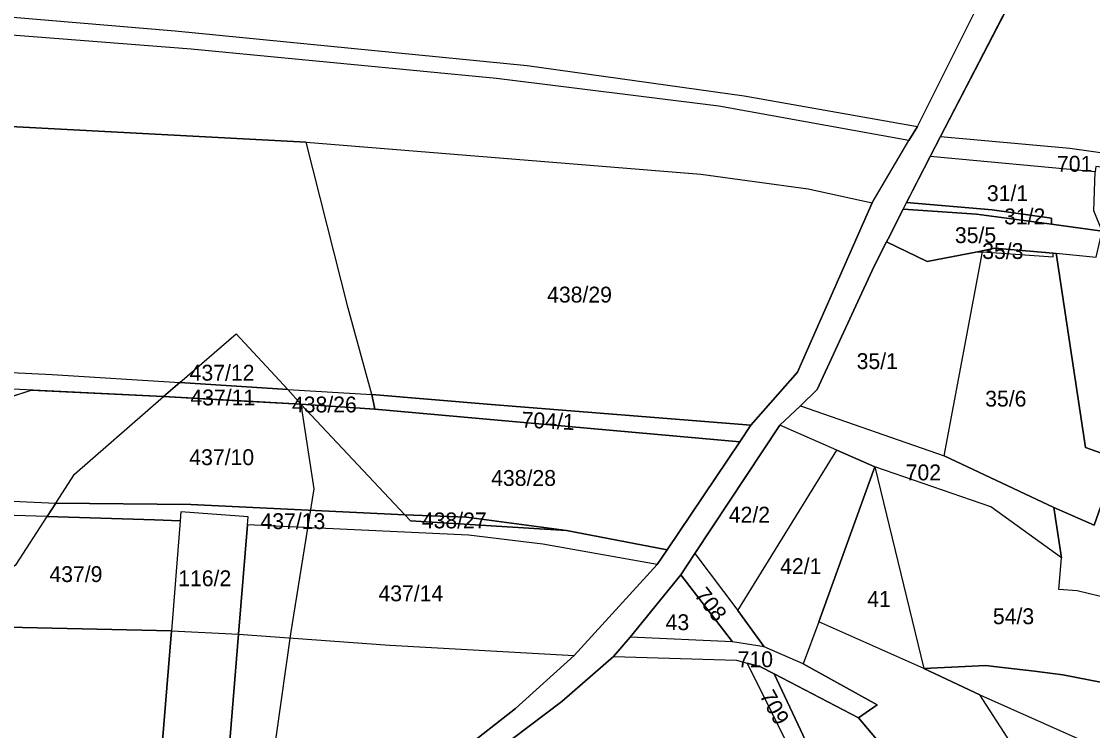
# Model space of a CAD drawing. Extents: x -629983 to -626385, y -1072828 to -1067897.
# Drawn here: x -627674 to -627471.3, y -1070394.2 to -1070260.1 of the extents above; entities that cross this region are included whole.
import ezdxf

# ---------------------------------------------------------------- set-up
doc = ezdxf.new("R2010")
doc.units = 0
for name, color, linetype in [('Parcela nároku', 7, 'Continuous'), ('Parcelní číslo', 7, 'Continuous'), ('Plocha PÚ', 7, 'Continuous'), ('Vnitřní obvod_šetřený', 7, 'Continuous')]:
    doc.layers.add(name, color=color, linetype=linetype)

msp = doc.modelspace()

# ---------------------------------------------------------------- linework, layer by layer
at = {"layer": 'Parcela nároku'}
for points in [[(-628010.32, -1070222.78), (-627867.35, -1070243.48), (-627800.2, -1070247.16), (-627750.66, -1070252.06), (-627712.43, -1070256.17), (-627644.93, -1070261.86), (-627578.29, -1070268.4), (-627537.22, -1070274.1), (-627504.39, -1070279.94), (-627482.04, -1070235.24), (-627493.99, -1070234.25), (-627560.1, -1070227.33), (-627685.83, -1070213.41), (-627710.8, -1070210.1), (-627839.49, -1070195.32), (-627852.52, -1070193.73), (-627931.37, -1070179.87)], [(-628010.32, -1070222.78), (-627867.35, -1070243.48), (-627800.2, -1070247.16), (-627750.66, -1070252.06), (-627712.43, -1070256.17), (-627644.93, -1070261.86), (-627578.29, -1070268.4), (-627537.22, -1070274.1), (-627504.39, -1070279.94), (-627506.01, -1070282.58), (-627542.01, -1070276.06), (-627584.08, -1070270.83), (-627641.87, -1070265.31), (-627692.85, -1070261.34), (-627706.57, -1070260.22), (-627765.59, -1070253.53), (-627842.38, -1070247.97), (-627872.06, -1070246.99), (-627936.13, -1070236.87)], [(-627675.73, -1070497.41), (-627670.84, -1070489.21), (-627664.39, -1070479.79), (-627651.75, -1070462.96), (-627646.33, -1070454.56), (-627642.78, -1070448.49), (-627642.71, -1070448.68), (-627639.15, -1070447.3), (-627640.32, -1070444.28), (-627635.77, -1070436.5), (-627632.18, -1070430.36), (-627626.49, -1070424.12), (-627596.54, -1070402.58), (-627580.46, -1070390.03), (-627569.41, -1070380), (-627553.68, -1070362.8), (-627551.79, -1070360), (-627538.05, -1070339.59), (-627535.93, -1070336.45), (-627527.1, -1070326.43), (-627512.99, -1070294.4), (-627506.01, -1070282.58), (-627504.39, -1070279.94), (-627482.04, -1070235.24)], [(-627943.87, -1070258.43), (-627852.12, -1070267.55), (-627762.73, -1070274.69), (-627694, -1070279.01), (-627620.1, -1070282.88), (-627545.39, -1070288.95), (-627525.09, -1070291.72), (-627512.99, -1070294.4), (-627506.01, -1070282.58), (-627542.01, -1070276.06), (-627584.08, -1070270.83), (-627641.87, -1070265.31), (-627692.85, -1070261.34), (-627706.57, -1070260.22), (-627765.59, -1070253.53), (-627842.38, -1070247.97), (-627872.06, -1070246.99), (-627936.13, -1070236.87)], [(-627484.54, -1070251.9), (-627500.04, -1070281.83), (-627501.98, -1070285.58), (-627506.48, -1070294.32), (-627507.13, -1070295.59), (-627509.97, -1070301.16), (-627510.28, -1070301.76), (-627512.6, -1070306.32), (-627523.41, -1070329.67), (-627526.53, -1070332.79), (-627530.45, -1070336.44), (-627546.52, -1070360.7), (-627549.2, -1070364.77), (-627558.79, -1070376.55), (-627561.95, -1070380.18), (-627571.72, -1070388.7), (-627596.73, -1070407.55)], [(-627693.61, -1070374.29), (-627645.62, -1070375.32), (-627649.31, -1070420.79), (-627636.65, -1070421.82), (-627632.91, -1070375.97), (-627604.25, -1070378.04), (-627569.41, -1070380), (-627580.46, -1070390.03), (-627596.54, -1070402.58), (-627626.49, -1070424.12), (-627639.33, -1070428.04), (-627666.89, -1070426.71), (-627676.98, -1070425.76)]]:
    msp.add_lwpolyline(points, dxfattribs=at)
for points in [[(-627477.24, -1070236.31), (-627484.54, -1070251.9), (-627500.04, -1070281.83), (-627475.57, -1070284), (-627464.35, -1070285.62), (-627429.37, -1070289.04), (-627418.41, -1070263.38), (-627409.42, -1070267.15), (-627420.23, -1070245.71), (-627451.48, -1070240.87)], [(-627694, -1070279.01), (-627762.73, -1070274.69), (-627852.12, -1070267.55), (-627857.41, -1070320.6), (-627807.86, -1070322.13), (-627780.69, -1070322.36), (-627715.75, -1070324.53), (-627668.16, -1070326.84), (-627643.99, -1070328.38), (-627633.37, -1070319.16), (-627623.56, -1070329.68), (-627607.68, -1070330.66), (-627612.15, -1070314.31), (-627620.1, -1070282.88)], [(-627975.41, -1070316.56), (-628013.39, -1070311.63), (-628064.17, -1070304.46), (-628158.28, -1070288.4), (-628169.7, -1070285.94), (-628193.03, -1070281.15), (-628197.85, -1070304.82), (-628163.72, -1070310.89), (-628107.67, -1070319.94), (-627998.49, -1070336.29), (-627905.29, -1070342.7), (-627827.64, -1070345.16), (-627715.35, -1070349), (-627667.5, -1070351.19), (-627663.96, -1070345.7), (-627647.13, -1070331.03), (-627719.77, -1070327.49), (-627789.19, -1070324.83), (-627857.63, -1070323.4), (-627930.45, -1070320.12)], [(-627464.35, -1070285.62), (-627429.37, -1070289.04), (-627431.24, -1070294.08), (-627443.18, -1070290.54), (-627458.17, -1070289.11), (-627470.63, -1070287.47), (-627470.75, -1070288.53), (-627501.98, -1070285.58), (-627500.04, -1070281.83), (-627475.57, -1070284)], [(-627545.39, -1070288.95), (-627525.09, -1070291.72), (-627512.99, -1070294.4), (-627527.1, -1070326.43), (-627535.93, -1070336.45), (-627585.09, -1070332.54), (-627607.68, -1070330.66), (-627612.15, -1070314.31), (-627620.1, -1070282.88)], [(-627479.02, -1070297.25), (-627479.04, -1070298.42), (-627469.42, -1070299.74), (-627471.01, -1070295.88), (-627470.75, -1070288.53), (-627501.98, -1070285.58), (-627506.48, -1070294.32), (-627490.24, -1070295.72)], [(-627469.42, -1070299.74), (-627479.04, -1070298.42), (-627493.23, -1070296.53), (-627507.13, -1070295.59), (-627509.97, -1070301.16), (-627510.28, -1070301.76), (-627502.57, -1070305.47), (-627493.05, -1070303.61), (-627489.75, -1070302.95), (-627478.71, -1070303.86), (-627478.14, -1070303.92), (-627470.55, -1070304.67)], [(-627506.48, -1070294.32), (-627507.13, -1070295.59), (-627493.23, -1070296.53), (-627479.04, -1070298.42), (-627479.02, -1070297.25), (-627490.24, -1070295.72)], [(-627461.62, -1070299.82), (-627455.76, -1070301), (-627448.6, -1070304.07), (-627442.44, -1070308.35), (-627438.26, -1070311.63), (-627421.91, -1070324.46), (-627422.06, -1070324.78), (-627425.91, -1070330.87), (-627428.78, -1070328.99), (-627431.33, -1070333.05), (-627437.16, -1070329.94), (-627441.2, -1070337.83), (-627442.96, -1070336.99), (-627445.44, -1070341.59), (-627447.23, -1070340.65), (-627450.6, -1070346.67), (-627449.35, -1070349.16), (-627453.84, -1070347.28), (-627472.61, -1070340.67), (-627478.14, -1070303.92), (-627470.55, -1070304.67), (-627469.42, -1070299.74)], [(-627512.6, -1070306.32), (-627523.41, -1070329.67), (-627526.53, -1070332.79), (-627499.33, -1070342.21), (-627492.09, -1070303.67), (-627493.05, -1070303.61), (-627502.57, -1070305.47), (-627510.28, -1070301.76)], [(-627478.14, -1070303.92), (-627472.61, -1070340.67), (-627453.84, -1070347.28), (-627449.35, -1070349.16), (-627426.96, -1070358.52), (-627429.07, -1070363.41), (-627455.93, -1070352.67), (-627456.37, -1070353.79), (-627462.61, -1070351.34), (-627468.81, -1070349.21), (-627470.94, -1070355.34), (-627478.59, -1070352.03), (-627499.33, -1070342.21), (-627492.09, -1070303.67), (-627478.71, -1070304.58), (-627478.71, -1070303.86)], [(-627478.71, -1070303.86), (-627489.75, -1070302.95), (-627493.05, -1070303.61), (-627492.09, -1070303.67), (-627478.71, -1070304.58)], [(-627998.49, -1070336.29), (-627905.29, -1070342.7), (-627827.64, -1070345.16), (-627715.35, -1070349), (-627667.5, -1070351.19), (-627669.14, -1070353.74), (-627747.72, -1070351.32), (-627834.23, -1070347.87), (-627862.19, -1070347.87), (-627903.57, -1070346.68), (-627931.89, -1070344.45), (-627993.13, -1070340.27), (-628115.46, -1070322.29), (-628198.34, -1070307.23), (-628197.85, -1070304.82), (-628163.72, -1070310.89), (-628107.67, -1070319.94)], [(-627903.57, -1070346.68), (-627931.89, -1070344.45), (-627993.13, -1070340.27), (-628115.46, -1070322.29), (-628198.34, -1070307.23), (-628203.34, -1070331.74), (-628177.12, -1070337.23), (-628130.58, -1070346.23), (-628080.75, -1070353.83), (-628037.7, -1070359.47), (-627955.53, -1070366.72), (-627892.97, -1070370.2), (-627840.14, -1070371.16), (-627807.49, -1070371.09), (-627701.48, -1070374.12), (-627693.61, -1070374.29), (-627674.98, -1070362.82), (-627669.14, -1070353.74), (-627747.72, -1070351.32), (-627834.23, -1070347.87), (-627862.19, -1070347.87)], [(-627633.37, -1070319.16), (-627623.56, -1070329.68), (-627643.99, -1070328.38)], [(-627668.16, -1070326.84), (-627643.99, -1070328.38), (-627647.13, -1070331.03), (-627719.77, -1070327.49), (-627789.19, -1070324.83), (-627857.63, -1070323.4), (-627857.41, -1070320.6), (-627807.86, -1070322.13), (-627780.69, -1070322.36), (-627715.75, -1070324.53)], [(-627623.56, -1070329.68), (-627621.11, -1070332.45), (-627647.13, -1070331.03), (-627643.99, -1070328.38)], [(-627623.56, -1070329.68), (-627607.68, -1070330.66), (-627607.12, -1070333.41), (-627621.11, -1070332.45)], [(-627663.96, -1070345.7), (-627647.13, -1070331.03), (-627621.11, -1070332.45), (-627601.45, -1070353.4), (-627641.91, -1070351.46), (-627667.5, -1070351.19)], [(-627607.12, -1070333.41), (-627538.05, -1070339.59), (-627551.79, -1070360), (-627570.84, -1070356.36), (-627589.76, -1070353.83), (-627601.45, -1070353.4), (-627621.11, -1070332.45)], [(-627607.68, -1070330.66), (-627585.09, -1070332.54), (-627535.93, -1070336.45), (-627538.05, -1070339.59), (-627607.12, -1070333.41)], [(-627526.53, -1070332.79), (-627499.33, -1070342.21), (-627478.59, -1070352.03), (-627477.14, -1070361.52), (-627490.53, -1070351.87), (-627512.45, -1070344.31), (-627519.69, -1070341.14), (-627530.45, -1070336.44)], [(-627530.45, -1070336.44), (-627546.52, -1070360.7), (-627538.42, -1070371.52), (-627519.69, -1070341.14)], [(-627519.69, -1070341.14), (-627512.45, -1070344.31), (-627523.07, -1070373.63), (-627526.06, -1070381.6), (-627533.41, -1070378.39), (-627538.42, -1070371.52)], [(-627523.07, -1070373.63), (-627512.45, -1070344.31), (-627503.17, -1070382.49)], [(-627428.34, -1070382.69), (-627459.6, -1070371.3), (-627474.17, -1070367.79), (-627477.66, -1070367.54), (-627477.14, -1070361.52), (-627490.53, -1070351.87), (-627512.45, -1070344.31), (-627503.17, -1070382.49), (-627491.48, -1070381.91), (-627489.96, -1070382.08), (-627482.22, -1070382.97), (-627478.87, -1070383.4), (-627476.87, -1070383.66), (-627447.43, -1070389.39), (-627446.08, -1070383.13), (-627429.59, -1070386.99), (-627427.82, -1070383.61)], [(-627477.66, -1070367.54), (-627477.14, -1070361.52), (-627478.59, -1070352.03), (-627470.94, -1070355.34), (-627468.81, -1070349.21), (-627462.61, -1070351.34), (-627456.37, -1070353.79), (-627455.93, -1070352.67), (-627429.07, -1070363.41), (-627426.11, -1070364.59), (-627430.93, -1070374.9), (-627424.08, -1070376.75), (-627419.9, -1070377.83), (-627432.7, -1070392.58), (-627429.59, -1070386.99), (-627427.82, -1070383.61), (-627428.34, -1070382.69), (-627459.6, -1070371.3), (-627474.17, -1070367.79)], [(-627600.39, -1070354.54), (-627570.84, -1070356.36), (-627551.79, -1070360), (-627553.68, -1070362.8), (-627575.31, -1070358.96), (-627589.4, -1070357.26), (-627631.22, -1070355.29), (-627631.1, -1070353.76), (-627643.8, -1070352.84), (-627643.94, -1070354.51), (-627648.82, -1070354.37), (-627669.14, -1070353.74), (-627667.5, -1070351.19), (-627641.91, -1070351.46), (-627601.45, -1070353.4)], [(-627643.94, -1070354.51), (-627645.62, -1070375.32), (-627632.91, -1070375.97), (-627631.22, -1070355.29), (-627631.1, -1070353.76), (-627643.8, -1070352.84)], [(-627693.61, -1070374.29), (-627674.98, -1070362.82), (-627669.14, -1070353.74), (-627648.82, -1070354.37), (-627643.94, -1070354.51), (-627645.62, -1070375.32)], [(-627601.45, -1070353.4), (-627589.76, -1070353.83), (-627570.84, -1070356.36), (-627600.39, -1070354.54)], [(-627631.22, -1070355.29), (-627632.91, -1070375.97), (-627604.25, -1070378.04), (-627569.41, -1070380), (-627553.68, -1070362.8), (-627575.31, -1070358.96), (-627589.4, -1070357.26)], [(-627549.2, -1070364.77), (-627546.52, -1070360.7), (-627538.42, -1070371.52), (-627533.41, -1070378.39), (-627539.38, -1070377.41)], [(-627549.2, -1070364.77), (-627539.38, -1070377.41), (-627558.79, -1070376.55)], [(-627523.07, -1070373.63), (-627526.06, -1070381.6), (-627512.05, -1070389.37), (-627515.53, -1070391.8), (-627509.05, -1070399.5), (-627481.79, -1070434.49), (-627478.35, -1070438.88), (-627472.89, -1070436.01), (-627477.9, -1070426.3), (-627471.88, -1070422.95), (-627485.49, -1070398.49), (-627492.61, -1070387.47), (-627503.17, -1070382.49)], [(-627645.62, -1070375.32), (-627632.91, -1070375.97), (-627636.65, -1070421.82), (-627649.31, -1070420.79)], [(-627539.38, -1070377.41), (-627558.79, -1070376.55), (-627561.95, -1070380.18), (-627538.65, -1070380.92), (-627536.65, -1070381.47), (-627534.08, -1070382.18), (-627531.55, -1070383.49), (-627515.53, -1070391.8), (-627512.05, -1070389.37), (-627526.06, -1070381.6), (-627533.41, -1070378.39)], [(-627550.24, -1070428.21), (-627547.59, -1070432.38), (-627567.3, -1070428.39), (-627579.32, -1070427.13), (-627578.85, -1070417.27), (-627604.65, -1070413.41), (-627596.73, -1070407.55), (-627571.72, -1070388.7), (-627561.95, -1070380.18), (-627538.65, -1070380.92), (-627536.65, -1070381.47), (-627527.29, -1070400.28), (-627520.07, -1070415.67), (-627527.83, -1070420.03), (-627532.81, -1070411.95), (-627539.12, -1070401.72), (-627556.41, -1070413.63), (-627549.89, -1070423.61), (-627547.92, -1070426.74)], [(-627531.55, -1070383.49), (-627534.08, -1070382.18), (-627536.65, -1070381.47), (-627527.29, -1070400.28), (-627524.58, -1070398.23)], [(-627482.22, -1070382.97), (-627489.96, -1070382.08), (-627491.48, -1070381.91), (-627503.17, -1070382.49), (-627492.61, -1070387.47), (-627443.88, -1070409.16), (-627432.7, -1070392.58), (-627447.43, -1070389.39), (-627476.87, -1070383.66), (-627478.87, -1070383.4)], [(-627515.53, -1070391.8), (-627531.55, -1070383.49), (-627524.58, -1070398.23), (-627527.29, -1070400.28), (-627520.07, -1070415.67), (-627509.42, -1070434.62), (-627506.5, -1070439.81), (-627503.29, -1070437.99), (-627497.86, -1070446.25), (-627495.48, -1070449.89), (-627478.35, -1070438.88), (-627481.79, -1070434.49), (-627509.05, -1070399.5)], [(-627492.61, -1070387.47), (-627443.88, -1070409.16), (-627459.21, -1070426.46), (-627472.89, -1070436.01), (-627477.9, -1070426.3), (-627471.88, -1070422.95), (-627485.49, -1070398.49)]]:
    msp.add_lwpolyline(points, close=True, dxfattribs=at)
at = {"layer": 'Plocha PÚ'}
for points in [[(-627584.22, -1070398.12), (-627571.72, -1070388.7), (-627561.95, -1070380.18), (-627558.79, -1070376.55), (-627549.2, -1070364.77), (-627546.52, -1070360.7), (-627530.45, -1070336.44), (-627526.53, -1070332.79), (-627523.41, -1070329.67), (-627512.6, -1070306.32), (-627510.28, -1070301.76), (-627509.97, -1070301.16), (-627507.13, -1070295.59), (-627501.98, -1070285.58), (-627500.04, -1070281.83), (-627484.54, -1070251.9)], [(-627687.01, -1070334.57), (-627672.18, -1070329.81), (-627647.13, -1070331.03), (-627634.12, -1070331.74), (-627621.11, -1070332.45), (-627618.64, -1070348.46), (-627623.07, -1070375.88), (-627628.47, -1070414.25)]]:
    msp.add_lwpolyline(points, dxfattribs=at)
at = {"layer": 'Vnitřní obvod_šetřený'}
for p, q in [((-627500.04, -1070281.83), (-627484.54, -1070251.9)), ((-627501.98, -1070285.58), (-627500.04, -1070281.83)), ((-627507.13, -1070295.59), (-627501.98, -1070285.58)), ((-627509.97, -1070301.16), (-627507.13, -1070295.59)), ((-627512.6, -1070306.32), (-627510.28, -1070301.76)), ((-627510.28, -1070301.76), (-627509.97, -1070301.16)), ((-627523.41, -1070329.67), (-627512.6, -1070306.32)), ((-627687.01, -1070334.57), (-627672.18, -1070329.81)), ((-627647.13, -1070331.03), (-627672.18, -1070329.81)), ((-627526.53, -1070332.79), (-627523.41, -1070329.67)), ((-627647.13, -1070331.03), (-627621.11, -1070332.45)), ((-627530.45, -1070336.44), (-627526.53, -1070332.79)), ((-627546.52, -1070360.7), (-627530.45, -1070336.44)), ((-627549.2, -1070364.77), (-627546.52, -1070360.7)), ((-627558.79, -1070376.55), (-627549.2, -1070364.77)), ((-627561.95, -1070380.18), (-627558.79, -1070376.55)), ((-627571.72, -1070388.7), (-627561.95, -1070380.18))]:
    msp.add_line(p, q, dxfattribs=at)
for points in [[(-627621.11, -1070332.45), (-627618.64, -1070348.46), (-627620.86, -1070362.17)], [(-627620.86, -1070362.17), (-627623.07, -1070375.88), (-627625.77, -1070395.06), (-627628.47, -1070414.25), (-627632.12, -1070425.38), (-627635.77, -1070436.5), (-627640.32, -1070444.28), (-627639.15, -1070447.3), (-627641.51, -1070456.58), (-627632.51, -1070442.99), (-627626.98, -1070430.39), (-627625.75, -1070428.38), (-627621.8, -1070425.36), (-627617.53, -1070422.04), (-627604.65, -1070413.41), (-627596.73, -1070407.55), (-627571.72, -1070388.7)]]:
    msp.add_lwpolyline(points, dxfattribs=at)

# ---------------------------------------------------------------- texts
at = {"layer": 'Parcelní číslo'}
for s, p in [('701', (-627477.99, -1070288.48)), ('31/1', (-627491.25, -1070294.05)), ('31/2', (-627488.01, -1070298.44)), ('35/5', (-627497.31, -1070301.98)), ('35/3', (-627492.14, -1070304.99)), ('438/29', (-627574.5, -1070313.23)), ('35/1', (-627515.91, -1070325.81)), ('437/12', (-627642.16, -1070328.01)), ('437/11', (-627642.02, -1070332.69)), ('35/6', (-627491.58, -1070332.92)), ('438/26', (-627622.8, -1070334.02)), ('437/10', (-627642.23, -1070343.99)), ('438/28', (-627585.09, -1070347.92)), ('702', (-627506.63, -1070346.87)), ('438/27', (-627598.22, -1070355.95)), ('42/2', (-627540.11, -1070354.86)), ('437/13', (-627628.76, -1070356.09)), ('437/9', (-627668.71, -1070366.11)), ('42/1', (-627530.4, -1070364.61)), ('116/2', (-627644.33, -1070366.9)), ('437/14', (-627606.43, -1070369.75)), ('41', (-627513.9, -1070370.81)), ('54/3', (-627490.12, -1070374.08)), ('43', (-627552.07, -1070375.21)), ('710', (-627538.43, -1070382.22))]:
    msp.add_text(s, height=3, dxfattribs=at).set_placement(p)
for s, rotation, p in [('704/1', 357.293, (-627579.39, -1070336.88)), ('708', 308.0012, (-627546.76, -1070368.61)), ('709', 298.5155, (-627534.36, -1070387.57))]:
    msp.add_text(s, height=3, rotation=rotation, dxfattribs=at).set_placement(p)

doc.saveas('drawing.dxf')
